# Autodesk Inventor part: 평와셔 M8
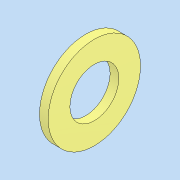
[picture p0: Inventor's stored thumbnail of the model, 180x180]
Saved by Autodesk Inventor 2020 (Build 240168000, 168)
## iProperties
Created: 2024-11
Part Number: 평와셔 M8
Material: 강철, 연강
Description: 평면 와셔
Document SubType Name: Modeling
Designer: 1강의실14
Density: 7.85 g/cm^3
Appearance: 기본값
Author: jhkim
Sending System: Autodesk Inventor 2025
Preprocessor: ST-DEVELOPER v20
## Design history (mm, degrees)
node "평와셔 M81"
node "솔리드1"
body "Solid1"
